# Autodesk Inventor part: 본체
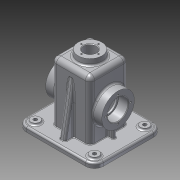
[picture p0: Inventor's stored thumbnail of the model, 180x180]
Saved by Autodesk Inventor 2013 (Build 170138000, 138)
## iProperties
Created: 2016-01
Part Number: 본체
Material: 알루미늄 6061
Document SubType Name: Modeling
Designer: User
Density: 2.71 g/cm^3
Mass: 803.235 g
Surface Area: 909.189 cm^2
Volume: 296.397 cm^3
Author: User
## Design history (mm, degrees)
sketch "스케치1"
  geometry: L1 (-32.5, -32.5)-(32.5, -32.5); L2 (32.5, -32.5)-(32.5, 32.5); L3 (32.5, 32.5)-(-32.5, 32.5); L4 (-32.5, 32.5)-(-32.5, -32.5); L5 (-32.5, -32.5)-(32.5, 32.5); L6 (32.5, -32.5)-(-32.5, 32.5); 1 further point
  constraints: 12 end point, 2 midpoint, 2 parallel, 1 horizontal, 1 perpendicular
  dimensions: "d0" = 65 distance of L1.start L1.end; "d2" = 65 distance of L1.end L2.end
extrude "돌출1" new body sketch "스케치1" stored distance "d3" = 100; taper "d4" = 0 deg
sketch "스케치2"
  geometry: L1 (-32.5, 32.5)-(-32.5, -32.5) reference; L2 (-65, 57.5)-(65, 57.5); L3 (65, 57.5)-(65, -57.5); L4 (65, -57.5)-(-65, -57.5); L5 (-65, -57.5)-(-65, 57.5); 3 further points
  constraints: 8 end point, 4 perpendicular, 2 midpoint, 1 horizontal alignment, 1 vertical alignment
  dimensions: "d5" = 130 distance of L2.start L2.end; "d6" = 115 distance of L2.end L3.end
extrude "돌출2" join sketch "스케치2" distance "d7" = 10; taper "d8" = 0 deg
fillet "모깎기1" dims "d9" = 8
fillet "모깎기2" dims "d10" = 8
sketch "스케치3"
  geometry: L1 (10, 82)-(10, -33) reference; L2 (10, 24.5)-(-45, 24.5); C1 r 27.5 at (-45, 24.5); 1 further point
  constraints: 2 end point, 1 centre point, 1 coincident, 1 midpoint, 1 perpendicular
  dimensions: "d11" = 55 distance of L2.start L2.end; "d12" = 55 diameter of C1
extrude "돌출3" join sketch "스케치3" distance "d13" = 15; taper "d14" = 0 deg
fillet "모깎기3" dims "d15" = 3
fillet "모깎기4" dims "d16" = 3
sketch "스케치4"
  geometry: C1 r 20 at (0, 0); 1 further point
  constraints: 1 centre point, 1 coincident
  dimensions: "d17" = 40 diameter of C1
extrude "돌출4" join sketch "스케치4" distance "d18" = 10; taper "d19" = 0 deg
sketch "스케치5"
  geometry: L1 (-27.5, -27.5)-(27.5, -27.5); L2 (27.5, -27.5)-(27.5, 27.5); L3 (27.5, 27.5)-(-27.5, 27.5); L4 (-27.5, 27.5)-(-27.5, -27.5); L5 (-27.5, -27.5)-(27.5, 27.5); L6 (27.5, -27.5)-(-27.5, 27.5); 1 further point
  constraints: 12 end point, 2 midpoint, 2 parallel, 1 horizontal, 1 perpendicular
  dimensions: "d21" = 55 distance of L2.end L3.end; "d23" = 55 distance of L1.end L2.end
extrude "돌출5" cut sketch "스케치5" distance "d24" = 105; taper "d25" = 0 deg
fillet "모깎기6" dims "d26" = 3
fillet "모깎기7" dims "d27" = 3
sketch "스케치6"
  geometry: C1 r 27.5 at (0, 0) reference; C2 r 17.5 at (0, 0); 1 further point
  constraints: 1 centre point, 1 coincident
  dimensions: "d28" = 35 diameter of C2
extrude "돌출6" cut sketch "스케치6" distance "d29" = 17; taper "d30" = 0 deg
sketch "스케치7"
  geometry: C1 r 17.5 at (0, 0) reference; C2 r 15 at (0, 0); 1 further point
  constraints: 1 centre point, 1 coincident
  dimensions: "d31" = 30 diameter of C2
extrude "돌출7" cut sketch "스케치7" distance "d32" = 3; taper "d33" = 0 deg
sketch "스케치8"
  geometry: C1 r 27.5 at (0, 0) reference; C2 r 17.5 at (0, 0); 1 further point
  constraints: 1 centre point, 1 coincident
  dimensions: "d34" = 35 diameter of C2
extrude "돌출8" cut sketch "스케치8" distance "d35" = 17; taper "d36" = 0 deg
sketch "스케치9"
  geometry: C1 r 17.5 at (0, 0) reference; C2 r 15 at (0, 0); 1 further point
  constraints: 1 centre point, 1 coincident
  dimensions: "d37" = 30 diameter of C2
extrude "돌출9" cut sketch "스케치9" distance "d38" = 3; taper "d39" = 0 deg
chamfer "모따기1" distance "d40" = 1; stored, may be unused: second distance "d41" = 2, angle "d42" = 45 deg
fillet "모깎기8" dims "d43" = 0.3
sketch "스케치10"
  geometry: L1 (65, 57.5)-(-65, 57.5) reference; L2 (-65, 57.5)-(-65, -57.5) reference; L3 (-65, -57.5)-(65, -57.5) reference; L4 (65, -57.5)-(65, 57.5) reference; L5 (-60, 52.5)-(-60, -52.5); L6 (-60, -52.5)-(60, -52.5); L7 (60, -52.5)-(60, 52.5); L8 (60, 52.5)-(-60, 52.5); 1 further point
  constraints: 8 end point, 3 parallel, 1 perpendicular
  dimensions: "d44" = 5 distance between parallel lines of L1 L8; "d45" = 5 distance between parallel lines of L2 L5; "d46" = 5 distance between parallel lines of L3 L6; "d47" = 5 distance between parallel lines of L4 L7
extrude "돌출10" cut sketch "스케치10" distance "d48" = 2; taper "d49" = 0 deg
fillet "모깎기9" dims "d50" = 10
fillet "모깎기10" dims "d51" = 10
fillet "모깎기11" dims "d52" = 15
sketch "스케치11" dims "d53" = 42
  geometry: L1 (0, 0)-(0, 21); C1 r 18.5 at (0, 0) reference; 2 further points
  constraints: 2 coincident, 2 end point, 1 vertical, 1 vertical alignment, 2 other
hole "구멍1" sketch "스케치11" at (0, 21) diameter "d54" = 3.242; stored, may be unused: countersink angle "d58" = 90 deg, drill point angle "d60" = 118 deg; dims "d55" = 8, "d56" = 4, "d57" = 2, "d59" = 10
sketch "스케치12"
  geometry: L1 (0, 57)-(-92, 57) reference; L2 (18, 4.5)-(18, 44.5) reference; 2 further points
  constraints: 1 other
  dimensions: "d64" = 32.5 distance from line of point (-8, 24.5) L1; "d65" = 26 distance from line of point (-8, 24.5) L2
feature "엠보싱1" sketch "스케치12" dims "d66" = 0.5, "d67" = 0
sketch "스케치13"
  geometry: C1 r 7.5 at (-50, 42.5); C2 r 7.5 at (-50, -42.5); C3 r 7.5 at (50, -42.5); C4 r 7.5 at (50, 42.5); A1 r 15 centre (50, 42.5) between (65, 42.5) and (50, 57.5) reference; A2 r 15 centre (-50, 42.5) between (-50, 57.5) and (-65, 42.5) reference; A3 r 15 centre (-50, -42.5) between (-65, -42.5) and (-50, -57.5) reference; A4 r 15 centre (50, -42.5) between (50, -57.5) and (65, -42.5) reference; 1 further point
  constraints: 4 centre point, 4 coincident
  dimensions: "d68" = 15 diameter of C1; "d69" = 15 diameter of C2; "d70" = 15 diameter of C3; "d71" = 15 diameter of C4
extrude "돌출11" join sketch "스케치13" distance "d72" = 3; taper "d73" = 0 deg
fillet "모깎기12" dims "d74" = 3
fillet "모깎기13" dims "d75" = 3
sketch "스케치14"
  geometry: C1 r 7.5 at (0, 0) reference; C2 r 3 at (0, 0); C3 r 7.5 at (0, 85) reference; C4 r 7.5 at (100, 85) reference; C5 r 7.5 at (100, 0) reference; C6 r 3 at (0, 85); C7 r 3 at (100, 85); C8 r 3 at (100, 0); 1 further point
  constraints: 4 centre point, 4 coincident
  dimensions: "d76" = 6 diameter of C2; "d77" = 6 diameter of C6; "d78" = 6 diameter of C7; "d79" = 6 diameter of C8
extrude "돌출12" cut sketch "스케치14" stored distance "d80" = 3; taper "d81" = 0 deg
sketch "스케치15"
  geometry: L1 (-32.5, -24.5)-(-32.5, 24.5) reference; L2 (50, -54.5)-(-50, -54.5) reference; L3 (-32.5, -3)-(-42.5, -3); L4 (-42.5, -3)-(-42.5, 3); L5 (-42.5, 3)-(-32.5, 3); 2 further points
  constraints: 6 end point, 2 perpendicular, 2 point on line, 1 horizontal alignment, 1 midpoint, 1 parallel
  dimensions: "d82" = 10 distance of L3.start L3.end; "d83" = 6 distance of L3.end L4.end
extrude "돌출13" join sketch "스케치15" stored distance "d84" = 3; taper "d85" = 0 deg
fillet "모깎기14" dims "d86" = 3
fillet "모깎기15" dims "d87" = 3
fillet "모깎기16" dims "d88" = 3
sketch "스케치16"
  geometry: L1 (-47.5, -50)-(-31.536, 40.538); L2 (-57.5, -58)-(-57.5, -53) reference; L3 (-32, -50)-(-53, -50) reference; 1 further point
  constraints: 2 end point, 1 point on line
  dimensions: "d89" = 10 distance from line of L1.start L2; "d90" = 10 deg angle of L2 L1
feature "리브1" sketch "스케치16" dims "d91" = 1, "d92" = 10, "d93" = 0, "d94" = 0, "d95" = 1, "d96" = 1
fillet "모깎기17" dims "d97" = 3
fillet "모깎기18" dims "d98" = 3
fillet "모깎기19" dims "d99" = 3
fillet "모깎기20" dims "d100" = 3
fillet "모깎기21" dims "d101" = 1
sketch "스케치17"
  geometry: C1 r 20 at (0, 0) reference; C2 r 10.5 at (0, 0)
  constraints: 1 centre point, 1 coincident
  dimensions: "d102" = 21 diameter of C2
extrude "돌출14" cut sketch "스케치17" stored distance "d103" = 3; taper "d104" = 0 deg
chamfer "모따기2" distance "d105" = 1; stored, may be unused: second distance "d106" = 2, angle "d107" = 45 deg
sketch "스케치18" dims "d108" = 29
  geometry: L1 (0, 0)-(0, 14.5); C1 r 11.5 at (0, 0) reference; 1 further point
  constraints: 2 coincident, 2 end point, 1 vertical, 1 vertical alignment, 2 other
hole "구멍2" sketch "스케치18" at (0, 14.5) diameter "d109" = 2.459; stored, may be unused: countersink angle "d113" = 90 deg, drill point angle "d115" = 118 deg; dims "d110" = 7, "d111" = 4, "d112" = 2, "d114" = 9
node "작업 평면1"
feature "면 기울기2" dims angle "d120" = 5 deg
fillet "모깎기22" dims "d121" = 3
node "솔리드1"
mirror "대칭1"
pattern_circular "원형 패턴1" dims angle "d62" = 360 deg
mirror "대칭2"
mirror "대칭3"
mirror "대칭4"
pattern_circular "원형 패턴2" dims angle "d117" = 360 deg
